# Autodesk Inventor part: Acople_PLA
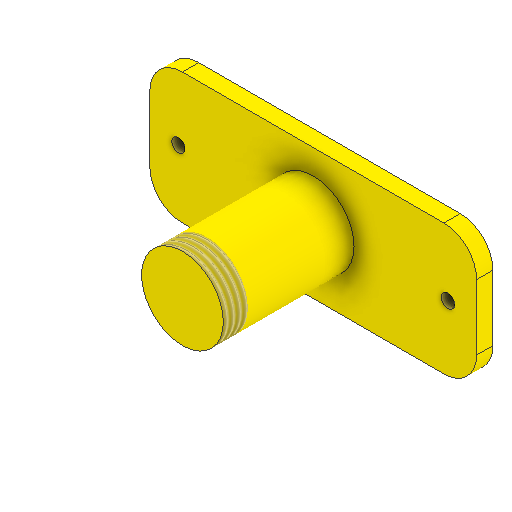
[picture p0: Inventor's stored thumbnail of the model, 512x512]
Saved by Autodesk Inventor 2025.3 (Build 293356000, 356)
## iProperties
Created: 2025-11
Part Number: Acople_PLA
Material: Genérico
Document SubType Name: Modeling
Designer: Dell
Density: 1 g/cm^3
Appearance: Valor por defecto
Mass: 312.59 g
Surface Area: 494.403 cm^2
Volume: 312.59 cm^3
Author: Dell
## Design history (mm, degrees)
sketch "Boceto1"
  geometry: L1 (-100, 40)-(100, 40); L2 (100, 40)-(100, -40); L3 (100, -40)-(-100, -40); L4 (-100, -40)-(-100, 40); L5 (-100, 40)-(100, -40); L6 (100, 40)-(-100, -40); C1 r 4.1 at (-82.5, 0); C2 r 4.1 at (82.5, 0); 1 further point
  constraints: 12 end point, 2 centre point, 2 midpoint, 2 parallel, 1 horizontal, 1 perpendicular
  dimensions: "d0" = 200 distance of L2.end L3.end; "d1" = 80 distance of L1.end L2.end
extrude "Extrusión1" new body sketch "Boceto1" distance "d5" = 10; taper "d6" = 0 deg
sketch "Boceto2"
  geometry: C1 r 25 at (0, 0); 1 further point
  constraints: 1 centre point, 1 coincident
  dimensions: "d7" = 50 diameter of C1
extrude "Extrusión2" join sketch "Boceto2" distance "d8" = 80; taper "d9" = 0 deg
feature "Rosca1" dims "d10" = 15, "d11" = 0
fillet "Empalme1" dims "d12" = 20
feature "Rosca2" dims "d13" = 80, "d14" = 0
feature "Rosca3" dims "d15" = 80, "d16" = 0
node "Sólido1"
